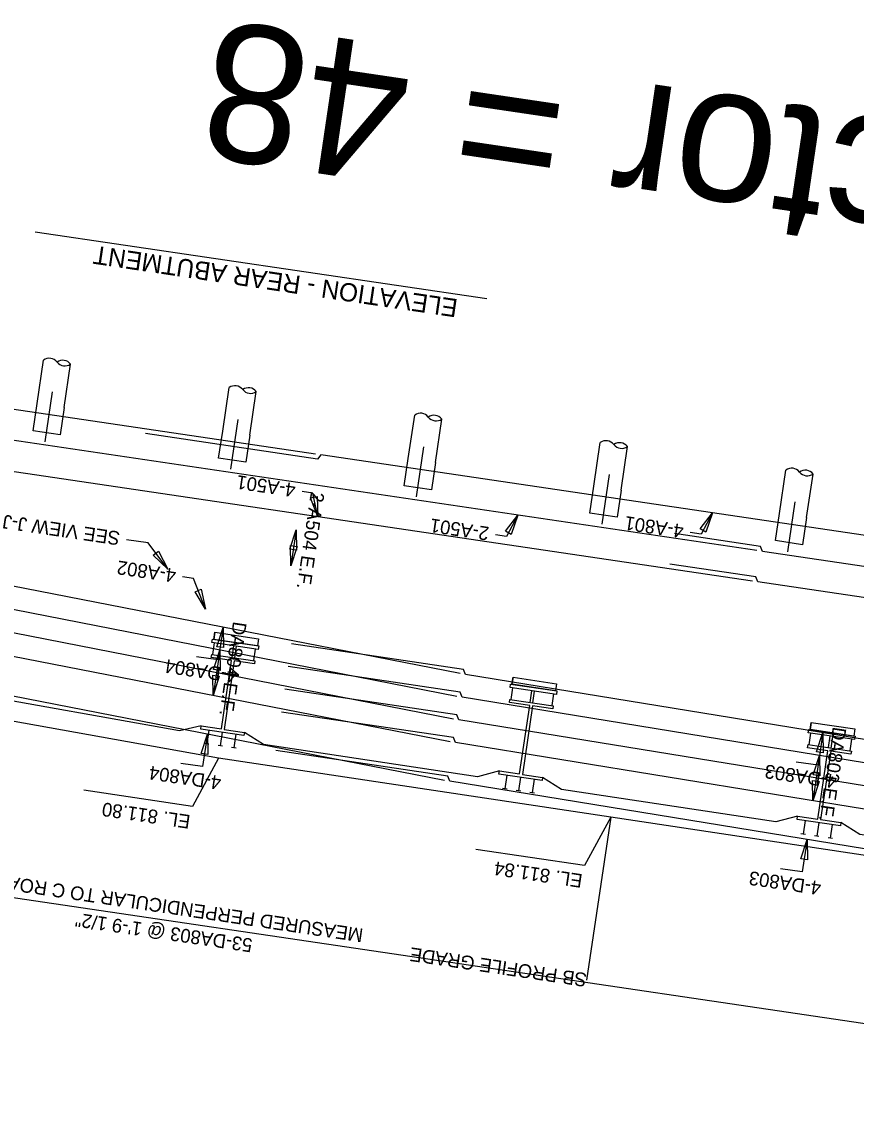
# Model space of a CAD drawing. Extents: x 1467956 to 1469946, y 573734 to 574139.
# Drawn here: x 1469019.53 to 1469049.93, y 574056.5 to 574095.95 of the extents above; entities that cross this region are included whole.
import ezdxf

# ---------------------------------------------------------------- set-up
doc = ezdxf.new("R2010")
doc.units = 0
for name, color, linetype in [('BR_P_Beam_Object', 7, 'Continuous'), ('BR_P_Beam_Stl_Det_Hidden', 7, 'Continuous'), ('BR_P_Brg_Pad_Object', 7, 'Continuous'), ('BR_P_Dia_Reinforcing', 7, 'Continuous'), ('BR_P_Gen_Text', 7, 'Continuous'), ('BR_P_Slab_Object', 7, 'Continuous'), ('BR_P_Sub_Deep_Centerline', 7, 'Continuous'), ('BR_P_Sub_Deep_Hidden', 7, 'Continuous'), ('BR_P_Sub_Deep_Object', 7, 'Continuous'), ('BR_P_Sub_Foot_Reinforcing', 7, 'Continuous'), ('BR_P_Sub_Text', 7, 'Continuous'), ('Default', 7, 'Continuous')]:
    doc.layers.add(name, color=color, linetype=linetype)

# ---------------------------------------------------------------- blocks, each defined once
blk = doc.blocks.new('arrowOhio')
at = {"layer": 'Default'}
blk.add_lwpolyline([(0.00381, 0.000635), (0.00381, -0.000635), (0, 0)], close=True, dxfattribs=at)

msp = doc.modelspace()

# ---------------------------------------------------------------- linework, layer by layer
at = {"layer": 'BR_P_Beam_Object'}
for p, q in [((1469026.434, 574072.804), (1469026.451, 574072.917)), ((1469027.172, 574072.694), (1469026.434, 574072.804)), ((1469026.451, 574072.917), (1469028.026, 574072.684)), ((1469026.803, 574070.201), (1469027.172, 574072.694)), ((1469027.271, 574072.68), (1469026.902, 574070.186)), ((1469028.009, 574072.571), (1469027.271, 574072.68)), ((1469028.026, 574072.684), (1469028.009, 574072.571)), ((1469037.295, 574071.165), (1469037.312, 574071.279)), ((1469037.312, 574071.279), (1469038.887, 574071.046)), ((1469038.033, 574071.056), (1469037.295, 574071.165)), ((1469037.664, 574068.563), (1469038.033, 574071.056)), ((1469038.132, 574071.042), (1469037.763, 574068.548)), ((1469038.87, 574070.932), (1469038.132, 574071.042)), ((1469038.887, 574071.046), (1469038.87, 574070.932)), ((1469026.048, 574070.197), (1469026.065, 574070.31)), ((1469027.623, 574069.964), (1469026.048, 574070.197)), ((1469026.065, 574070.31), (1469026.803, 574070.201)), ((1469026.341, 574070.153), (1469026.268, 574069.659)), ((1469026.836, 574070.08), (1469026.762, 574069.586)), ((1469026.902, 574070.186), (1469027.64, 574070.077)), ((1469027.64, 574070.077), (1469027.623, 574069.964)), ((1469026.35, 574069.647), (1469026.185, 574069.671)), ((1469027.33, 574070.007), (1469027.257, 574069.512)), ((1469048.154, 574069.517), (1469048.171, 574069.631)), ((1469048.171, 574069.631), (1469049.746, 574069.397)), ((1469026.845, 574069.573), (1469026.68, 574069.598)), ((1469027.339, 574069.5), (1469027.175, 574069.524)), ((1469048.892, 574069.408), (1469048.154, 574069.517)), ((1469048.523, 574066.914), (1469048.892, 574069.408)), ((1469048.992, 574069.393), (1469048.622, 574066.9)), ((1469049.73, 574069.284), (1469048.992, 574069.393)), ((1469049.746, 574069.397), (1469049.73, 574069.284)), ((1469036.909, 574068.558), (1469036.926, 574068.672)), ((1469038.484, 574068.325), (1469036.909, 574068.558)), ((1469036.926, 574068.672), (1469037.664, 574068.563)), ((1469037.202, 574068.515), (1469037.129, 574068.02)), ((1469037.697, 574068.442), (1469037.623, 574067.947)), ((1469037.763, 574068.548), (1469038.501, 574068.439)), ((1469038.501, 574068.439), (1469038.484, 574068.325)), ((1469038.191, 574068.369), (1469038.118, 574067.874)), ((1469037.211, 574068.008), (1469037.046, 574068.033)), ((1469037.706, 574067.935), (1469037.541, 574067.959)), ((1469038.2, 574067.862), (1469038.035, 574067.886)), ((1469047.768, 574066.91), (1469047.785, 574067.024)), ((1469049.344, 574066.677), (1469047.768, 574066.91)), ((1469047.785, 574067.024), (1469048.523, 574066.914)), ((1469048.061, 574066.867), (1469047.988, 574066.372)), ((1469048.622, 574066.9), (1469049.36, 574066.79)), ((1469048.556, 574066.794), (1469048.483, 574066.299)), ((1469049.051, 574066.721), (1469048.977, 574066.226)), ((1469049.36, 574066.79), (1469049.344, 574066.677)), ((1469048.071, 574066.36), (1469047.906, 574066.385)), ((1469048.565, 574066.287), (1469048.4, 574066.311)), ((1469049.06, 574066.214), (1469048.895, 574066.238))]:
    msp.add_line(p, q, dxfattribs=at)
at = {"layer": 'BR_P_Beam_Stl_Det_Hidden'}
for p, q in [((1469026.492, 574072.911), (1469026.554, 574073.333)), ((1469027.189, 574072.808), (1469027.251, 574073.23)), ((1469027.288, 574072.793), (1469027.35, 574073.216)), ((1469027.985, 574072.69), (1469028.047, 574073.112)), ((1469037.353, 574071.273), (1469037.415, 574071.695)), ((1469038.05, 574071.17), (1469038.112, 574071.592)), ((1469038.149, 574071.155), (1469038.211, 574071.577)), ((1469038.846, 574071.052), (1469038.908, 574071.474)), ((1469048.212, 574069.625), (1469048.275, 574070.047)), ((1469048.909, 574069.521), (1469048.972, 574069.944)), ((1469049.008, 574069.507), (1469049.071, 574069.929)), ((1469049.705, 574069.404), (1469049.768, 574069.826))]:
    msp.add_line(p, q, dxfattribs=at)
at = {"layer": 'BR_P_Brg_Pad_Object'}
for p, q in [((1469026.563, 574073.722), (1469026.525, 574073.464)), ((1469026.457, 574073.348), (1469026.476, 574073.471)), ((1469028.144, 574073.098), (1469026.457, 574073.348)), ((1469026.476, 574073.471), (1469028.163, 574073.222)), ((1469028.151, 574073.487), (1469028.113, 574073.229)), ((1469028.163, 574073.222), (1469028.144, 574073.098)), ((1469037.424, 574072.083), (1469037.386, 574071.826)), ((1469037.318, 574071.71), (1469037.337, 574071.833)), ((1469039.005, 574071.46), (1469037.318, 574071.71)), ((1469037.337, 574071.833), (1469039.024, 574071.583)), ((1469039.012, 574071.848), (1469038.974, 574071.591)), ((1469039.024, 574071.583), (1469039.005, 574071.46)), ((1469048.284, 574070.435), (1469048.246, 574070.178)), ((1469048.178, 574070.061), (1469048.196, 574070.185)), ((1469049.865, 574069.812), (1469048.178, 574070.061)), ((1469048.196, 574070.185), (1469049.883, 574069.935)), ((1469049.872, 574070.2), (1469049.833, 574069.943)), ((1469049.883, 574069.935), (1469049.865, 574069.812))]:
    msp.add_line(p, q, dxfattribs=at)
for points in [[(1469028.151, 574073.487), (1469028.113, 574073.229), (1469026.525, 574073.464), (1469026.563, 574073.722)], [(1469039.012, 574071.848), (1469038.974, 574071.591), (1469037.386, 574071.826), (1469037.424, 574072.083)], [(1469049.872, 574070.2), (1469049.833, 574069.943), (1469048.246, 574070.178), (1469048.284, 574070.435)]]:
    msp.add_lwpolyline(points, close=True, dxfattribs=at)
at = {"layer": 'BR_P_Dia_Reinforcing'}
for p, q in [((1469035.5, 574072.215), (1469013.917, 574076.431)), ((1469035.378, 574071.387), (1469013.795, 574075.603)), ((1469035.255, 574070.56), (1469013.672, 574074.776)), ((1469035.133, 574069.732), (1469013.55, 574073.948)), ((1469035.624, 574072.371), (1469029.359, 574073.299)), ((1469034.925, 574068.328), (1469013.342, 574072.545)), ((1469035.502, 574071.544), (1469029.237, 574072.471)), ((1469035.698, 574072.185), (1469035.624, 574072.371)), ((1469057.382, 574068.654), (1469035.698, 574072.185)), ((1469035.379, 574070.716), (1469029.114, 574071.644)), ((1469035.575, 574071.358), (1469035.502, 574071.544)), ((1469057.26, 574067.826), (1469035.575, 574071.358)), ((1469035.257, 574069.889), (1469028.992, 574070.816)), ((1469035.453, 574070.53), (1469035.379, 574070.716)), ((1469057.137, 574066.999), (1469035.453, 574070.53)), ((1469035.33, 574069.703), (1469035.257, 574069.889)), ((1469057.015, 574066.171), (1469035.33, 574069.703)), ((1469035.049, 574068.485), (1469028.784, 574069.413)), ((1469035.123, 574068.299), (1469035.049, 574068.485)), ((1469056.807, 574064.767), (1469035.123, 574068.299))]:
    msp.add_line(p, q, dxfattribs=at)
at = {"layer": 'BR_P_Gen_Text'}
for p, q in [((1469036.469, 574085.858), (1469020.024, 574088.293)), ((1469030.136, 574078.787), (1469029.74, 574078.845)), ((1469030.312, 574077.925), (1469030.136, 574078.787)), ((1469037.601, 574077.983), (1469037.182, 574077.209)), ((1469044.69, 574078.071), (1469044.271, 574077.297)), ((1469029.527, 574077.451), (1469029.334, 574076.142)), ((1469037.182, 574077.209), (1469036.787, 574077.268)), ((1469044.271, 574077.297), (1469043.875, 574077.355)), ((1469024.139, 574076.976), (1469023.348, 574077.093)), ((1469024.855, 574076.013), (1469024.139, 574076.976)), ((1469025.783, 574075.677), (1469025.388, 574075.736)), ((1469026.225, 574074.562), (1469025.783, 574075.677)), ((1469026.867, 574073.901), (1469026.691, 574072.714)), ((1469026.691, 574072.714), (1469025.9, 574072.831)), ((1469026.745, 574073.074), (1469026.499, 574071.419)), ((1469070.259, 574056.497), (1468978.025, 574070.152)), ((1469026.292, 574070.015), (1469026.116, 574068.828)), ((1469048.708, 574070.066), (1469048.533, 574068.879)), ((1469048.586, 574069.239), (1469048.341, 574067.584)), ((1469026.116, 574068.828), (1469025.325, 574068.945)), ((1469026.696, 574069.14), (1469025.745, 574067.382)), ((1469048.533, 574068.879), (1469047.741, 574068.996)), ((1469025.745, 574067.382), (1469021.788, 574067.967)), ((1469040.98, 574066.988), (1469040.028, 574065.229)), ((1469048.133, 574066.18), (1469047.957, 574064.993)), ((1469040.028, 574065.229), (1469036.071, 574065.815)), ((1469047.957, 574064.993), (1469047.166, 574065.11))]:
    msp.add_line(p, q, dxfattribs=at)
at = {"layer": 'BR_P_Slab_Object'}
for p, q in [((1469026.696, 574069.14), (1468981.648, 574077.187)), ((1469040.98, 574066.988), (1469026.696, 574069.14)), ((1469071.925, 574062.316), (1469040.98, 574066.988))]:
    msp.add_line(p, q, dxfattribs=at)
for points in [[(1469026.065, 574070.31), (1469025.28, 574070.134), (1469017.509, 574071.522), (1469016.821, 574072.002)], [(1469036.926, 574068.672), (1469036.135, 574068.455), (1469028.332, 574069.631), (1469027.64, 574070.077)], [(1469047.785, 574067.024), (1469046.996, 574066.817), (1469039.193, 574067.994), (1469038.501, 574068.439)], [(1469058.646, 574065.385), (1469057.857, 574065.177), (1469050.054, 574066.355), (1469049.36, 574066.79)]]:
    msp.add_lwpolyline(points, dxfattribs=at)
at = {"layer": 'BR_P_Sub_Deep_Centerline'}
for p, q in [((1469020.388, 574080.657), (1469020.657, 574082.471)), ((1469027.148, 574079.657), (1469027.417, 574081.47)), ((1469033.908, 574078.656), (1469034.176, 574080.47)), ((1469040.667, 574077.655), (1469040.936, 574079.469)), ((1469047.427, 574076.655), (1469047.696, 574078.468))]:
    msp.add_line(p, q, dxfattribs=at)
at = {"layer": 'BR_P_Sub_Deep_Hidden'}
for p, q in [((1469019.943, 574081.06), (1469020.089, 574082.05)), ((1469021.078, 574081.903), (1469020.932, 574080.914)), ((1469020.932, 574080.914), (1469019.943, 574081.06)), ((1469026.702, 574080.06), (1469026.849, 574081.049)), ((1469027.838, 574080.902), (1469027.692, 574079.913)), ((1469027.692, 574079.913), (1469026.702, 574080.06)), ((1469033.462, 574079.059), (1469033.608, 574080.048)), ((1469034.598, 574079.902), (1469034.451, 574078.913)), ((1469034.451, 574078.913), (1469033.462, 574079.059)), ((1469040.222, 574078.058), (1469040.368, 574079.047)), ((1469041.357, 574078.901), (1469041.211, 574077.912)), ((1469041.211, 574077.912), (1469040.222, 574078.058)), ((1469046.981, 574077.058), (1469047.128, 574078.047)), ((1469048.117, 574077.9), (1469047.97, 574076.911)), ((1469047.97, 574076.911), (1469046.981, 574077.058))]:
    msp.add_line(p, q, dxfattribs=at)
at = {"layer": 'BR_P_Sub_Deep_Object'}
for p, q in [((1469020.089, 574082.05), (1469020.323, 574083.632)), ((1469021.078, 574081.903), (1469021.313, 574083.486)), ((1469026.849, 574081.049), (1469027.083, 574082.632)), ((1469027.838, 574080.902), (1469028.072, 574082.485)), ((1469033.608, 574080.048), (1469033.843, 574081.631)), ((1469034.598, 574079.902), (1469034.832, 574081.484)), ((1469040.368, 574079.047), (1469040.602, 574080.63)), ((1469041.357, 574078.901), (1469041.592, 574080.484)), ((1469047.128, 574078.047), (1469047.362, 574079.629)), ((1469048.117, 574077.9), (1469048.351, 574079.483))]:
    msp.add_line(p, q, dxfattribs=at)
for centre, start, end in [((1469020.532, 574083.336), 37.976, 125.1816), ((1469021.027, 574083.263), 37.976, 125.1816), ((1469021.104, 574083.782), 217.976, 305.1816), ((1469027.292, 574082.335), 37.976, 125.1816), ((1469027.787, 574082.262), 37.976, 125.1816), ((1469027.863, 574082.782), 217.976, 305.1816), ((1469034.052, 574081.335), 37.976, 125.1816), ((1469034.546, 574081.261), 37.976, 125.1816), ((1469034.623, 574081.781), 217.976, 305.1816), ((1469040.811, 574080.334), 37.976, 125.1816), ((1469041.306, 574080.261), 37.976, 125.1816), ((1469041.383, 574080.78), 217.976, 305.1816), ((1469047.571, 574079.333), 37.976, 125.1816), ((1469048.065, 574079.26), 37.976, 125.1816), ((1469048.142, 574079.779), 217.976, 305.1816)]:
    msp.add_arc(centre, 0.362, start, end, dxfattribs=at)
at = {"layer": 'BR_P_Sub_Foot_Reinforcing'}
for points in [[(1469030.229, 574080.212), (1469004.495, 574084.021), (1469004.371, 574083.865), (1468998.106, 574084.792)], [(1469046.308, 574076.694), (1469010.886, 574081.938), (1469010.812, 574082.124), (1469007.68, 574082.588)], [(1469046.144, 574075.581), (1469010.721, 574080.825), (1469010.648, 574081.011), (1469007.515, 574081.475)], [(1469056.161, 574076.372), (1469030.427, 574080.182), (1469030.303, 574080.026), (1469024.038, 574080.953)], [(1469082.126, 574071.391), (1469046.506, 574076.665), (1469046.433, 574076.85), (1469043.3, 574077.314)], [(1469081.962, 574070.278), (1469046.341, 574075.552), (1469046.268, 574075.738), (1469043.135, 574076.201)]]:
    msp.add_lwpolyline(points, dxfattribs=at)
at = {"layer": 'BR_P_Sub_Text'}
msp.add_line((1469040.98, 574066.988), (1469040.101, 574061.053), dxfattribs=at)

# ---------------------------------------------------------------- block references
at = {"layer": 'BR_P_Gen_Text'}
for p, xscale, yscale, rotation in [((1469030.312, 574077.925), 191.49567999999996, 191.49568, 101.57876932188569), ((1469037.601, 574077.983), 191.49568000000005, 191.49568000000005, -118.42123067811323), ((1469044.69, 574078.071), 191.49568000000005, 191.49568000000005, -118.42123067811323), ((1469029.527, 574077.451), 191.49568000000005, 191.49568, -98.42123067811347), ((1469029.334, 574076.142), 191.49568000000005, 191.49568, 81.57876932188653), ((1469024.855, 574076.013), 191.49568000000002, 191.49568000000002, 126.57876932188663), ((1469026.225, 574074.562), 191.49568000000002, 191.49568000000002, 111.57876932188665), ((1469026.867, 574073.901), 191.49568000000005, 191.49568, -98.42123067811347), ((1469026.745, 574073.074), 191.49568000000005, 191.49568, -98.42123067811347), ((1469026.499, 574071.419), 191.49568000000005, 191.49568, 81.57876932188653), ((1469026.292, 574070.015), 191.49568000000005, 191.49568, -98.42123067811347), ((1469048.708, 574070.066), 191.49568000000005, 191.49568, -98.42123067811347), ((1469048.586, 574069.239), 191.49568000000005, 191.49568, -98.42123067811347), ((1469048.341, 574067.584), 191.49568000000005, 191.49568, 81.57876932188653), ((1469048.133, 574066.18), 191.49568000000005, 191.49568, -98.42123067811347)]:
    msp.add_blockref('arrowOhio', p, dxfattribs=dict(at, xscale=xscale, yscale=yscale, rotation=rotation))

# ---------------------------------------------------------------- texts
for s, height, rotation, p in [('Scale Factor = 48', 4.99999, 171.5788, (1469078.57, 574088.343)), ('ELEVATION - REAR ABUTMENT', 0.665, 171.5788, (1469035.442, 574085.842)), ('4-A501', 0.5, 171.5788, (1469029.529, 574079.129)), ('2-A504 E.F.', 0.5, 261.5788, (1469030.066, 574078.861)), ('SEE VIEW J-J', 0.5, 171.5788, (1469023.137, 574077.377)), ('4-A801', 0.5, 171.5788, (1469043.664, 574077.639)), ('2-A501', 0.5, 171.5788, (1469036.576, 574077.551)), ('4-A802', 0.5, 171.5788, (1469025.177, 574076.02)), ('DA804 E.F.', 0.5, 261.5788, (1469027.231, 574074.132)), ('4-DA804', 0.5, 171.5788, (1469027.396, 574072.361)), ('DA803 E.F.', 0.5, 261.5788, (1469049.072, 574070.297)), ('4-DA804', 0.5, 171.5788, (1469026.821, 574068.475)), ('4-DA803', 0.5, 171.5788, (1469049.246, 574068.525)), ('EL. 811.80', 0.5, 171.5788, (1469025.697, 574067.059)), ('EL. 811.84', 0.5, 171.5788, (1469039.98, 574064.907)), ('MEASURED PERPENDICULAR TO C ROADWAY', 0.5, 171.5788, (1469031.992, 574062.924)), ('4-DA803', 0.5, 171.5788, (1469048.671, 574064.639)), ('53-DA803 @ 1\'-9 1/2"', 0.5, 171.5788, (1469027.959, 574062.557)), ('SB PROFILE GRADE ', 0.5, 171.5788, (1469040.138, 574061.3))]:
    msp.add_text(s, height=height, rotation=rotation, dxfattribs=at).set_placement(p)

doc.saveas('drawing.dxf')
